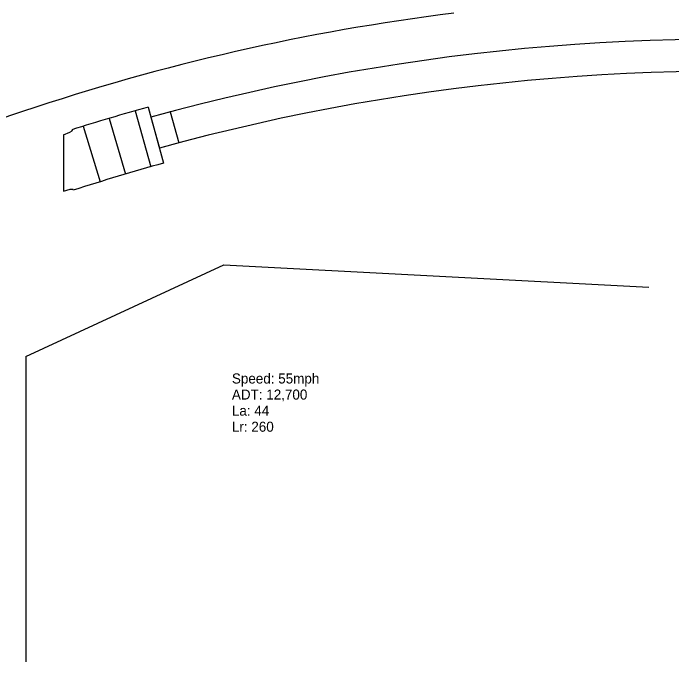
# Model space of a CAD drawing. Extents: x 24523748 to 24530451, y 6406056 to 6407468.
# Drawn here: x 24527443.1 to 24527934.6, y 6406983.3 to 6407467.5 of the extents above; entities that cross this region are included whole.
import ezdxf

# ---------------------------------------------------------------- set-up
doc = ezdxf.new("R2010")
doc.units = 0
for name, color, linetype in [('DisROW Existing', 7, 'Continuous'), ('dsnNonPlotable', 7, 'Continuous'), ('EdgePaved', 7, 'Continuous'), ('Joints', 7, 'Continuous')]:
    doc.layers.add(name, color=color, linetype=linetype)

msp = doc.modelspace()

# ---------------------------------------------------------------- linework, layer by layer
at = {"layer": 'DisROW Existing'}
msp.add_line((24527452.46, 6407211.3), (24527452.46, 6406983.31), dxfattribs=at)
msp.add_lwpolyline([(24527452.46, 6407211.3), (24527600.26, 6407279.75), (24527917.42, 6407263.02)], dxfattribs=at)
at = {"layer": 'dsnNonPlotable'}
for radius, start, end in [(1649.63, 97.11247, 120.07637), (1617.62, 62.73567, 105.42738), (1593.62, 62.73567, 105.42738)]:
    msp.add_arc((24527976.2, 6405830.59), radius, start, end, dxfattribs=at)
at = {"layer": 'EdgePaved'}
for p, q in [((24527543.84, 6407397.35), (24527555.37, 6407355.57)), ((24527560.35, 6407393.89), (24527566.74, 6407370.76)), ((24527545.88, 6407389.93), (24527552.27, 6407366.8)), ((24527486.94, 6407380.53), (24527487.21, 6407379.67)), ((24527480.79, 6407376.79), (24527480.79, 6407334.73)), ((24527487.96, 6407335.34), (24527487.68, 6407336.19))]:
    msp.add_line(p, q, dxfattribs=at)
for points in [[(24527480.79, 6407376.79), (24527485.47, 6407378.58), (24527487.21, 6407379.67)], [(24527480.79, 6407334.73), (24527485.62, 6407336.04), (24527487.68, 6407336.19)]]:
    msp.add_lwpolyline(points, dxfattribs=at)
for radius, start, end in [(1625.32, 105.42738, 107.51898), (1617.62, 104.89608, 105.42738), (1593.62, 104.88808, 105.42738), (1581.98, 105.42738, 107.97645)]:
    msp.add_arc((24527976.2, 6405830.59), radius, start, end, dxfattribs=at)
at = {"layer": 'Joints'}
for p, q in [((24527534.09, 6407394.63), (24527545.88, 6407352.92)), ((24527514.64, 6407389), (24527526.95, 6407347.44)), ((24527495.27, 6407383.13), (24527508.09, 6407341.72))]:
    msp.add_line(p, q, dxfattribs=at)

# ---------------------------------------------------------------- texts
at = {"layer": 'dsnNonPlotable'}
for s, p in [('Speed: 55mph', (24527606.33, 6407191.07)), ('ADT: 12,700', (24527606.33, 6407179.07)), ('La: 44', (24527606.33, 6407167.07)), ('Lr: 260', (24527606.33, 6407155.07))]:
    msp.add_text(s, height=7.5, dxfattribs=at).set_placement(p)

doc.saveas('drawing.dxf')
